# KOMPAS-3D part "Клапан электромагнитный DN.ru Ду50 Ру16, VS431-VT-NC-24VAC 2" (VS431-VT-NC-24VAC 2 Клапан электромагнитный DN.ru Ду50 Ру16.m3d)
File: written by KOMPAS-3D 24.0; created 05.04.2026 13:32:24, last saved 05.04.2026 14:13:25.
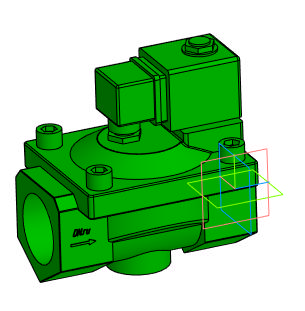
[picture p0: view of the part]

Document properties: Автор: artio; Полное имя файла: C:\Users\artio\OneDrive\Рабочий стол\Клапан электромагнитный DN.ru\VS431\VS431-VT-NC\VS431-VT-NC-24VAC\Ду50\VS431-VT-NC-24VAC 2 Клапан электромагнитный DN.ru Ду50 Ру16.m3d

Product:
- Body: Тело 1  | qty 1
    Масса: 6.703651
- Part/product: Клапан электромагнитный DN.ru Ду50 Ру16  | designation VS431-VT-NC-24VAC 2
    Масса: 3.341
    Раздел спецификации: Прочие изделия
    Примечание: D130-05517
    additional columns: ef56311e-7521-43dc-8291-0e6108b3d81d; artio; c; Шероховатость не задана; Да

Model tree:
1. Операция без истории:1

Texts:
  VS431-VT-NC-24VAC 2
